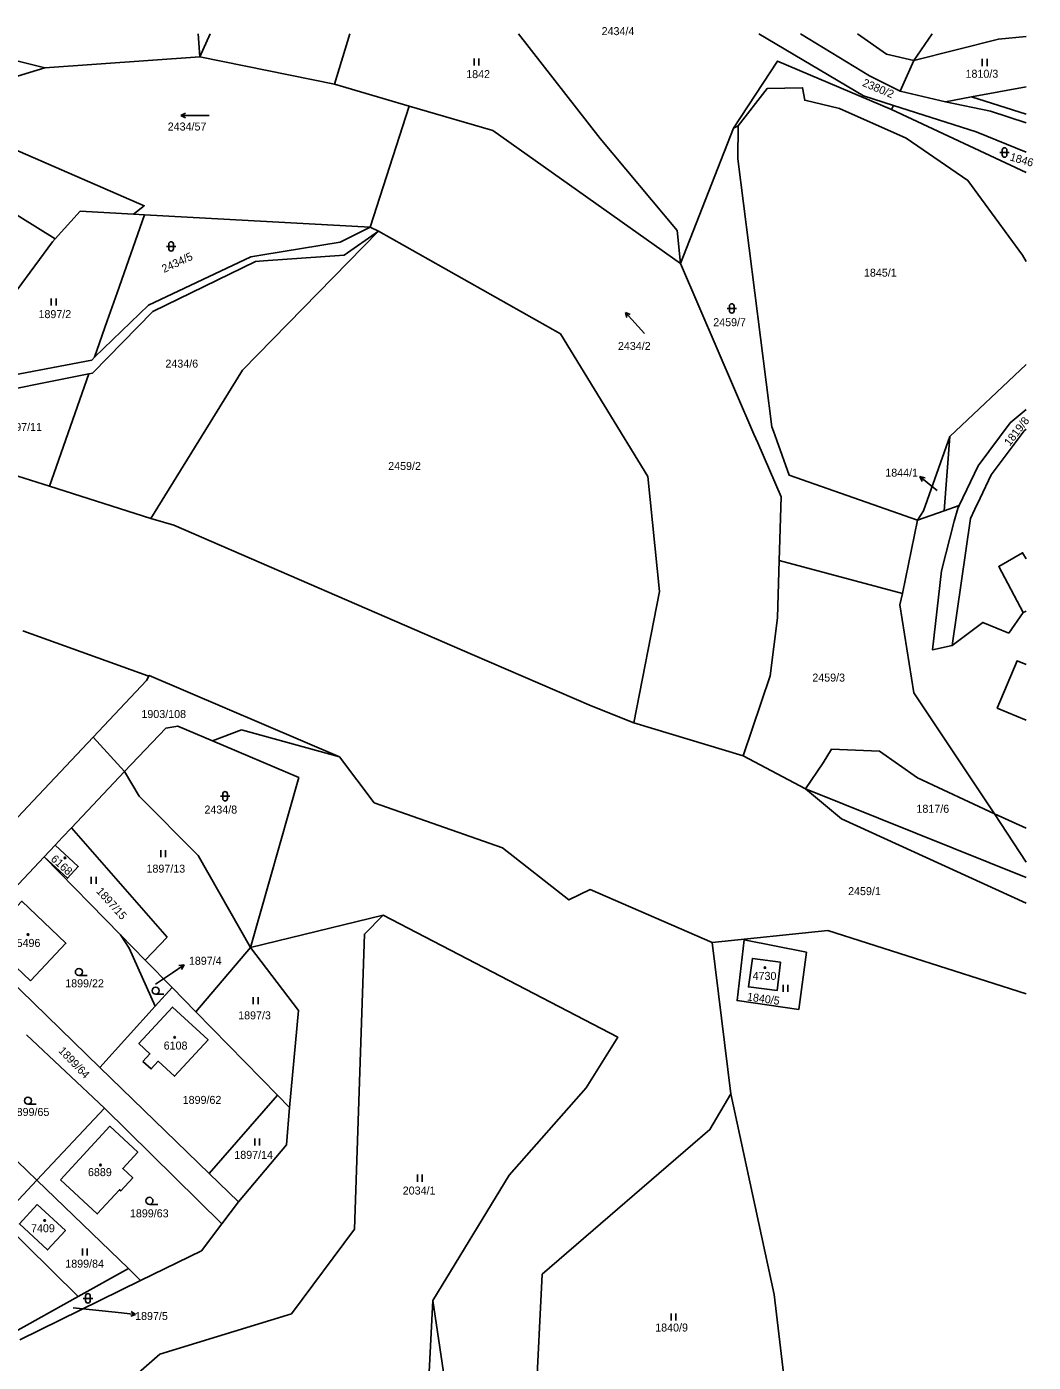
# Model space of a CAD drawing. Extents: x -667048 to -665920, y -1108425 to -1107247.
# Drawn here: x -666139.7 to -665925.8, y -1107531.2 to -1107247.5 of the extents above; entities that cross this region are included whole.
import ezdxf

# ---------------------------------------------------------------- set-up
doc = ezdxf.new("R2010")
doc.units = 0
for name, color, linetype in [('Default', 7, 'Continuous'), ('Hranice parcel', 7, 'Continuous'), ('Parcelní čísla', 7, 'Continuous'), ('Pop_ PČ_ popisy', 7, 'Continuous'), ('Značky budov', 7, 'Continuous'), ('Značky kultur', 7, 'Continuous')]:
    doc.layers.add(name, color=color, linetype=linetype)

# ---------------------------------------------------------------- blocks, each defined once
blk = doc.blocks.new('8.021')
at = {"layer": 'Default'}
for p, q in [((3018, -10), (2039, 490)), ((-2982, -10), (3018, -10)), ((3018, -10), (2039, -510))]:
    blk.add_line(p, q, dxfattribs=at)
blk = doc.blocks.new('3.041')
at = {"layer": 'Default'}
blk.add_line((8, 0), (1758, 0), dxfattribs=at)
blk.add_circle((8, 750), 750, dxfattribs=at)
blk = doc.blocks.new('4.021')
at = {"layer": 'Default'}
blk.add_circle((-7, 1), 175, dxfattribs=at)
blk = doc.blocks.new('3.161')
at = {"layer": 'Default'}
for p, q in [((-1000, 1000), (1000, 1000)), ((-500, 1500), (-500, 500)), ((500, 500), (500, 1500))]:
    blk.add_line(p, q, dxfattribs=at)
for centre, start, end in [((0, 1500), 0, 180), ((0, 500), 180, 359.98789)]:
    blk.add_arc(centre, 500, start, end, dxfattribs=at)
blk = doc.blocks.new('10291')
at = {"layer": 'Default'}
for p, q in [((0, 3001), (-500, 2001)), ((0, 1), (0, 3001)), ((0, 3001), (500, 2001))]:
    blk.add_line(p, q, dxfattribs=at)
blk = doc.blocks.new('3.061')
at = {"layer": 'Default'}
for p, q in [((-511, -1), (-511, 1499)), ((489, -1), (489, 1499))]:
    blk.add_line(p, q, dxfattribs=at)

msp = doc.modelspace()

# ---------------------------------------------------------------- linework, layer by layer
at = {"layer": 'Hranice parcel'}
for points in [[(-666158.97, -1107250.39), (-666135.82, -1107256.22)], [(-666102.88, -1107253.87), (-666103.26, -1107248.98)], [(-666102.88, -1107253.87), (-666100.71, -1107248.98)], [(-666070.99, -1107248.98), (-666074.24, -1107259.69)], [(-666000.76, -1107297.8), (-666001.47, -1107290.75), (-666017.83, -1107271.19), (-666035.19, -1107248.98)], [(-665984.1, -1107248.98), (-665961.87, -1107262.15), (-665955.48, -1107264.2)], [(-665954.1, -1107261.15), (-665960.56, -1107257.88), (-665975.26, -1107248.98)], [(-665963.11, -1107248.98), (-665956.94, -1107253.33), (-665951.18, -1107254.64)], [(-665947.26, -1107248.98), (-665951.18, -1107254.64)], [(-665951.18, -1107254.64), (-665933.2, -1107250.11), (-665927.32, -1107249.55)], [(-666135.82, -1107256.22), (-666102.88, -1107253.87)], [(-666102.88, -1107253.87), (-666074.24, -1107259.69)], [(-666163.06, -1107264.49), (-666135.82, -1107256.22)], [(-665955.88, -1107265.09), (-665980.12, -1107254.78), (-665989.51, -1107269.03)], [(-665954.1, -1107261.15), (-665951.18, -1107254.64)], [(-666074.24, -1107259.69), (-666058.4, -1107264.33)], [(-665927.32, -1107297.38), (-665928.07, -1107296), (-665939.69, -1107280.11), (-665952.83, -1107271.15), (-665966.95, -1107264.88), (-665974.33, -1107263.1), (-665974.82, -1107260.44), (-665982.36, -1107260.63), (-665988.5, -1107268.53)], [(-665944.43, -1107263.43), (-665954.1, -1107261.15)], [(-665938.93, -1107262.4), (-665944.43, -1107263.43)], [(-665927.32, -1107260.23), (-665938.93, -1107262.4)], [(-665927.32, -1107266.07), (-665938.93, -1107262.4)], [(-666163.06, -1107264.49), (-666114.71, -1107285.52), (-666117.01, -1107287.33)], [(-666058.4, -1107264.33), (-666066.69, -1107290.07)], [(-666058.4, -1107264.33), (-666056.71, -1107264.82), (-666040.6, -1107269.54), (-666000.76, -1107297.8)], [(-665955.48, -1107264.2), (-665955.88, -1107265.09)], [(-665927.32, -1107278.45), (-665955.88, -1107265.09)], [(-665955.48, -1107264.2), (-665937.91, -1107269.81), (-665927.32, -1107274.16)], [(-665944.43, -1107263.43), (-665934.85, -1107265.45), (-665927.32, -1107267.88)], [(-666133.6, -1107292.51), (-666170.11, -1107269.86)], [(-666000.76, -1107297.8), (-665989.51, -1107269.03)], [(-665989.51, -1107269.03), (-665988.5, -1107268.53)], [(-665988.5, -1107268.53), (-665988.53, -1107275.55), (-665981.33, -1107332.5), (-665981.02, -1107333.37), (-665980.31, -1107335.34), (-665977.69, -1107342.7), (-665950.41, -1107352.3)], [(-666117.01, -1107287.33), (-666128.31, -1107286.69), (-666133.6, -1107292.51)], [(-666120.45, -1107303.99), (-666114.66, -1107287.46)], [(-666114.66, -1107287.46), (-666117.01, -1107287.33)], [(-666066.69, -1107290.07), (-666114.66, -1107287.46)], [(-666113.28, -1107351.95), (-666093.81, -1107320.44), (-666064.9, -1107290.93)], [(-666066.69, -1107290.07), (-666073.07, -1107293.23)], [(-666072.21, -1107295.98), (-666064.9, -1107290.93)], [(-666064.9, -1107290.93), (-666066.69, -1107290.07)], [(-666010.65, -1107395.32), (-666005.19, -1107367.43), (-666007.69, -1107343), (-666026.23, -1107312.73), (-666064.9, -1107290.93)], [(-666153.04, -1107318.64), (-666134.21, -1107293.18), (-666133.6, -1107292.51)], [(-666073.07, -1107293.23), (-666089.48, -1107295.95), (-666092.04, -1107296.38)], [(-666092.04, -1107296.38), (-666113.79, -1107306.65), (-666125.26, -1107317.7)], [(-666091.07, -1107297.33), (-666089.35, -1107297.21), (-666072.21, -1107295.98)], [(-666126.48, -1107321.18), (-666125.73, -1107321.04), (-666112.86, -1107307.95), (-666091.07, -1107297.33)], [(-665979.76, -1107360.83), (-665979.38, -1107347.34), (-665984.33, -1107335.86), (-665985.13, -1107334.03), (-666000.76, -1107297.8)], [(-666125.26, -1107317.7), (-666122.55, -1107309.97), (-666120.45, -1107303.99)], [(-666125.26, -1107317.7), (-666125.87, -1107318.29), (-666152.4, -1107323.34)], [(-665943.49, -1107334.51), (-665927.32, -1107319.26)], [(-666152, -1107326.31), (-666126.48, -1107321.18)], [(-666126.48, -1107321.18), (-666134.85, -1107345.07)], [(-665927.32, -1107328.79), (-665930.66, -1107331.64), (-665937.46, -1107340.74)], [(-665927.32, -1107332.98), (-665927.72, -1107333.32), (-665934.7, -1107342.64)], [(-665943.49, -1107334.51), (-665949.08, -1107350.28), (-665950.41, -1107352.3)], [(-665944.74, -1107350.3), (-665943.49, -1107334.51)], [(-666150.17, -1107340.2), (-666145.64, -1107341.64), (-666134.85, -1107345.07)], [(-665937.46, -1107340.74), (-665941.53, -1107349.18)], [(-665934.7, -1107342.64), (-665937.06, -1107347.6), (-665938.17, -1107349.95)], [(-666134.85, -1107345.07), (-666113.28, -1107351.95)], [(-665944.74, -1107350.3), (-665950.41, -1107352.3)], [(-665943.03, -1107378.9), (-665947.2, -1107379.82), (-665945.31, -1107363.04), (-665942.63, -1107352.49), (-665941.84, -1107349.81)], [(-665941.53, -1107349.18), (-665944.74, -1107350.3)], [(-665938.17, -1107349.95), (-665939.09, -1107351.93), (-665943.03, -1107378.9)], [(-665941.84, -1107349.81), (-665941.53, -1107349.18)], [(-666113.28, -1107351.95), (-666108.42, -1107353.38), (-666045, -1107380.86), (-666019.75, -1107391.71), (-666010.65, -1107395.32)], [(-665950.41, -1107352.3), (-665953.54, -1107367.87)], [(-665979.76, -1107360.83), (-665979.83, -1107363.23), (-665980.11, -1107373.03), (-665981.69, -1107385.39), (-665987.43, -1107402.33)], [(-665953.54, -1107367.87), (-665979.76, -1107360.83)], [(-665927.92, -1107371.93), (-665933.12, -1107362.11), (-665928.07, -1107359.23), (-665927.32, -1107360.54)], [(-665953.54, -1107367.87), (-665954.17, -1107370.31)], [(-665954.17, -1107370.31), (-665951.16, -1107388.94), (-665934.01, -1107414.69)], [(-665927.92, -1107371.93), (-665930.98, -1107376.27)], [(-665927.32, -1107371.59), (-665927.92, -1107371.93)], [(-666113.67, -1107385.26), (-666113.91, -1107385.35), (-666140.49, -1107375.81)], [(-665930.98, -1107376.27), (-665936.5, -1107374.01), (-665943.03, -1107378.9)], [(-665927.32, -1107394.75), (-665933.43, -1107392.19), (-665929.24, -1107382.15), (-665927.32, -1107382.96)], [(-666125.58, -1107398.37), (-666114.25, -1107386.32), (-666113.67, -1107385.26)], [(-666113.67, -1107385.26), (-666073.2, -1107402.54)], [(-666010.65, -1107395.32), (-665987.43, -1107402.33)], [(-666125.58, -1107398.37), (-666138.32, -1107411.91), (-666164.02, -1107439.23)], [(-666118.87, -1107405.71), (-666125.58, -1107398.37)], [(-666100.17, -1107399.18), (-666107.58, -1107396.04), (-666110.1, -1107396.5), (-666118.87, -1107405.71)], [(-666094.03, -1107396.83), (-666100.17, -1107399.18)], [(-666073.2, -1107402.54), (-666094.03, -1107396.83)], [(-666100.17, -1107399.18), (-666081.88, -1107406.92), (-666092.15, -1107443.08)], [(-665934.01, -1107414.69), (-665950.36, -1107407.04), (-665958.49, -1107401.35), (-665968.63, -1107400.9), (-665970.46, -1107403.84)], [(-665994.04, -1107442.03), (-666019.91, -1107430.77), (-666024.45, -1107432.95), (-666038.57, -1107421.89), (-666065.82, -1107412.34), (-666073.2, -1107402.54)], [(-665987.43, -1107402.33), (-665974.2, -1107409.35)], [(-665970.46, -1107403.84), (-665974.2, -1107409.35)], [(-666118.87, -1107405.71), (-666130.15, -1107417.67)], [(-666092.15, -1107443.08), (-666103.21, -1107423.52), (-666115.78, -1107410.89), (-666118.87, -1107405.71)], [(-665974.2, -1107409.35), (-665927.32, -1107428.19)], [(-665927.32, -1107433.64), (-665966.57, -1107415.71), (-665974.2, -1107409.35)], [(-665927.32, -1107417.74), (-665934.01, -1107414.69)], [(-665927.32, -1107424.91), (-665934.01, -1107414.69)], [(-666133.64, -1107421.31), (-666132.06, -1107419.66), (-666130.15, -1107417.67)], [(-666130.15, -1107417.67), (-666109.81, -1107440.87)], [(-666135.96, -1107423.82), (-666133.64, -1107421.31)], [(-666133.64, -1107421.31), (-666128.73, -1107425.88), (-666131.02, -1107428.34), (-666135.96, -1107423.82)], [(-666135.96, -1107423.82), (-666152.36, -1107441.13)], [(-666119.76, -1107440.36), (-666135.96, -1107423.82)], [(-666138.86, -1107450.11), (-666143.48, -1107445.75), (-666142.79, -1107445.03), (-666147.55, -1107440.53), (-666140.7, -1107433.25), (-666131.34, -1107442.15), (-666138.86, -1107450.11)], [(-666078.53, -1107587.54), (-666084.83, -1107586.87), (-666095.21, -1107561.99), (-666119.98, -1107544.08), (-666122.25, -1107538.94), (-666111.42, -1107529.45), (-666083.41, -1107520.89), (-666070.02, -1107502.86), (-666067.9, -1107440.22), (-666063.91, -1107436.22)], [(-666063.91, -1107436.22), (-666092.15, -1107443.08)], [(-666063.91, -1107436.22), (-666014.07, -1107462.11), (-666020.79, -1107472.88), (-666037.16, -1107491.42), (-666053.35, -1107518.04)], [(-666152.36, -1107441.13), (-666124.15, -1107468.52)], [(-666114.49, -1107445.74), (-666119.76, -1107440.36)], [(-666119.76, -1107440.36), (-666117.92, -1107443.19), (-666112.4, -1107455.54)], [(-666109.81, -1107440.87), (-666114.49, -1107445.74)], [(-665927.32, -1107452.9), (-665969.47, -1107439.44), (-665994.04, -1107442.03)], [(-666092.15, -1107443.08), (-666103.73, -1107456.73)], [(-666083.8, -1107477.08), (-666081.91, -1107456.41), (-666092.15, -1107443.08)], [(-665994.04, -1107442.03), (-665990.06, -1107474.14)], [(-665975.61, -1107456.24), (-665988.72, -1107454.32), (-665987.21, -1107441.41), (-665973.99, -1107444.08), (-665975.61, -1107456.24)], [(-666108.79, -1107451.56), (-666114.49, -1107445.74)], [(-665979.47, -1107446.15), (-665985.45, -1107445.38), (-665986.31, -1107451.42), (-665980.19, -1107452.19), (-665979.47, -1107446.15)], [(-666112.4, -1107455.54), (-666108.79, -1107451.56)], [(-666108.79, -1107451.56), (-666103.73, -1107456.73)], [(-666124.15, -1107468.52), (-666112.4, -1107455.54)], [(-666115.01, -1107467.31), (-666113.48, -1107465.65), (-666115.84, -1107463.46), (-666108.67, -1107455.7), (-666101.13, -1107462.69), (-666108.29, -1107470.42), (-666111.73, -1107467.23), (-666113.22, -1107468.84), (-666115.01, -1107467.31)], [(-666103.73, -1107456.73), (-666086.41, -1107474.42)], [(-666139.75, -1107461.63), (-666123.15, -1107477.16)], [(-666124.15, -1107468.52), (-666100.93, -1107491.06)], [(-666086.41, -1107474.42), (-666100.93, -1107491.06)], [(-666086.41, -1107474.42), (-666083.8, -1107477.08)], [(-665927.32, -1107631.76), (-665951.75, -1107613.17), (-665956.95, -1107610.08), (-665980.3, -1107596.2), (-666020.72, -1107556.63), (-666026.53, -1107548.48), (-666031.47, -1107539.46), (-666030.14, -1107512.46), (-665994.5, -1107481.72), (-665990.06, -1107474.14)], [(-665990.06, -1107474.14), (-665980.83, -1107516.75), (-665973.63, -1107577.61), (-665969.22, -1107589.23), (-665953.21, -1107608.85), (-665927.32, -1107624.25)], [(-666137.54, -1107492.5), (-666154.01, -1107476.64)], [(-666123.15, -1107477.16), (-666137.54, -1107492.5)], [(-666098.24, -1107501.79), (-666123.15, -1107477.16)], [(-666094.7, -1107497.11), (-666084.44, -1107485), (-666083.8, -1107477.08)], [(-666132.53, -1107492.4), (-666122, -1107481.04), (-666116.08, -1107486.54), (-666119.28, -1107490.02), (-666117.15, -1107491.99), (-666119.7, -1107494.77), (-666119.96, -1107494.53), (-666124.69, -1107499.65), (-666132.53, -1107492.4)], [(-666100.93, -1107491.06), (-666094.7, -1107497.11)], [(-666145.36, -1107500.84), (-666137.54, -1107492.5)], [(-666137.54, -1107492.5), (-666118.07, -1107511.27)], [(-666137.43, -1107497.64), (-666131.44, -1107503.16), (-666135.23, -1107507.29), (-666141.24, -1107501.78), (-666137.43, -1107497.64)], [(-666098.24, -1107501.79), (-666094.7, -1107497.11)], [(-666128.73, -1107517.2), (-666145.36, -1107500.84)], [(-666115.52, -1107513.82), (-666102.55, -1107507.47), (-666098.24, -1107501.79)], [(-666118.07, -1107511.27), (-666128.73, -1107517.2)], [(-666115.52, -1107513.82), (-666118.07, -1107511.27)], [(-666141.12, -1107526.37), (-666115.52, -1107513.82)], [(-666128.73, -1107517.2), (-666142.67, -1107524.95)], [(-666053.35, -1107518.04), (-666055.04, -1107549.73), (-666078.53, -1107587.54)], [(-666046.71, -1107562.75), (-666053.35, -1107518.04)]]:
    msp.add_lwpolyline(points, dxfattribs=at)
at = {"layer": 'Pop_ PČ_ popisy'}
for points in [[(-665946.21, -1107346), (-665947.54, -1107344.93)], [(-666112.29, -1107450.83), (-666108.7, -1107448.41)], [(-666129.83, -1107519.58), (-666119.52, -1107520.67)]]:
    msp.add_lwpolyline(points, dxfattribs=at)

# ---------------------------------------------------------------- block references
for p, xscale, yscale, rotation in [((-665947.54, -1107344.93), 0.001, 0.0010000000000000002, 51.000000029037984), ((-666108.7, -1107448.41), 0.0010000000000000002, 0.0010000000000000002, -55.99999991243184), ((-666119.52, -1107520.67), 0.0010000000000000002, 0.0010000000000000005, -95.99999998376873)]:
    msp.add_blockref('10291', p, dxfattribs=dict(at, xscale=xscale, yscale=yscale, rotation=rotation))
at = {"layer": 'Značky budov', "xscale": 0.0010000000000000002, "yscale": 0.0010000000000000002}
for p in [(-666131.53, -1107424.03), (-666139.4, -1107440.31), (-665982.78, -1107447.33), (-666108.24, -1107462.14), (-666123.99, -1107489.26), (-666135.87, -1107501.05)]:
    msp.add_blockref('4.021', p, dxfattribs=at)
at = {"layer": 'Značky kultur', "xscale": 0.0010000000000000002, "yscale": 0.0010000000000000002}
for name, p in [('3.061', (-666044.07, -1107255.73)), ('3.061', (-665936.1, -1107255.83)), ('3.161', (-665931.88, -1107275.2)), ('3.161', (-666108.98, -1107295.14)), ('3.061', (-666133.94, -1107306.71)), ('3.161', (-665989.85, -1107308.32)), ('3.161', (-666097.53, -1107411.94)), ('3.061', (-666110.68, -1107423.87)), ('3.061', (-666125.44, -1107429.57)), ('3.041', (-666128.59, -1107449.01)), ('3.041', (-666112.28, -1107452.98)), ('3.061', (-665978.41, -1107452.49)), ('3.061', (-666091.01, -1107455.09)), ('3.041', (-666139.42, -1107476.35)), ('3.061', (-666090.72, -1107485.15)), ('3.061', (-666056.14, -1107492.81)), ('3.041', (-666113.6, -1107497.62)), ('3.061', (-666127.32, -1107508.46)), ('3.161', (-666126.66, -1107518.58)), ('3.061', (-666002.24, -1107522.27))]:
    msp.add_blockref(name, p, dxfattribs=at)
at = {"layer": 'Značky kultur', "xscale": 0.0010000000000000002}
for p, yscale, rotation in [((-666103.88, -1107266.36), 0.0010000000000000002, 180), ((-666010.43, -1107310.43), 0.001, 131.999999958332)]:
    msp.add_blockref('8.021', p, dxfattribs=dict(at, yscale=yscale, rotation=rotation))

# ---------------------------------------------------------------- texts
at = {"layer": 'Parcelní čísla'}
for s, p in [('2434/4', (-666017.51, -1107249.27)), ('1842', (-666046.28, -1107258.4)), ('1810/3', (-665940.18, -1107258.32)), ('2434/57', (-666109.71, -1107269.53)), ('1845/1', (-665961.76, -1107300.57)), ('1897/2', (-666137.17, -1107309.38)), ('2459/7', (-665993.79, -1107311.09)), ('2434/2', (-666014.04, -1107316.14)), ('2434/6', (-666110.2, -1107319.89)), ('1897/11', (-666144.65, -1107333.35)), ('2459/2', (-666062.86, -1107341.63)), ('1844/1', (-665957.23, -1107343.05)), ('2459/3', (-665972.74, -1107386.58)), ('1903/108', (-666115.3, -1107394.32)), ('2434/8', (-666101.91, -1107414.61)), ('1817/6', (-665950.61, -1107414.44)), ('1897/13', (-666114.22, -1107427.16)), ('2459/1', (-665965.13, -1107431.94)), ('5496', (-666141.82, -1107442.94)), ('1897/4', (-666105.21, -1107446.73)), ('1899/22', (-666131.49, -1107451.52)), ('4730', (-665985.42, -1107449.94)), ('1897/3', (-666094.74, -1107458.32)), ('6108', (-666110.57, -1107464.74)), ('1899/62', (-666106.53, -1107476.28)), ('1899/65', (-666143.08, -1107478.84)), ('1897/14', (-666095.56, -1107487.95)), ('6889', (-666126.66, -1107491.62)), ('2034/1', (-666059.77, -1107495.54)), ('1899/63', (-666117.74, -1107500.38)), ('7409', (-666138.76, -1107503.54)), ('1899/84', (-666131.48, -1107511.07)), ('1897/5', (-666116.64, -1107522.18)), ('1840/9', (-666006.12, -1107524.63))]:
    msp.add_text(s, height=1.7, dxfattribs=at).set_placement(p)
for s, rotation, p in [('2380/2', 337, (-665962.25, -1107260)), ('1846', 344, (-665930.89, -1107275.85)), ('2434/5', 25, (-666110.5, -1107299.8)), ('1819/8', 52, (-665930.78, -1107336.67)), ('6168', 318, (-666134.68, -1107424.47)), ('1897/15', 312, (-666125, -1107431.21)), ('1840/5', 352, (-665986.69, -1107454.29)), ('1899/64', 314, (-666133.05, -1107465.13))]:
    msp.add_text(s, height=1.7, rotation=rotation, dxfattribs=at).set_placement(p)

doc.saveas('drawing.dxf')
